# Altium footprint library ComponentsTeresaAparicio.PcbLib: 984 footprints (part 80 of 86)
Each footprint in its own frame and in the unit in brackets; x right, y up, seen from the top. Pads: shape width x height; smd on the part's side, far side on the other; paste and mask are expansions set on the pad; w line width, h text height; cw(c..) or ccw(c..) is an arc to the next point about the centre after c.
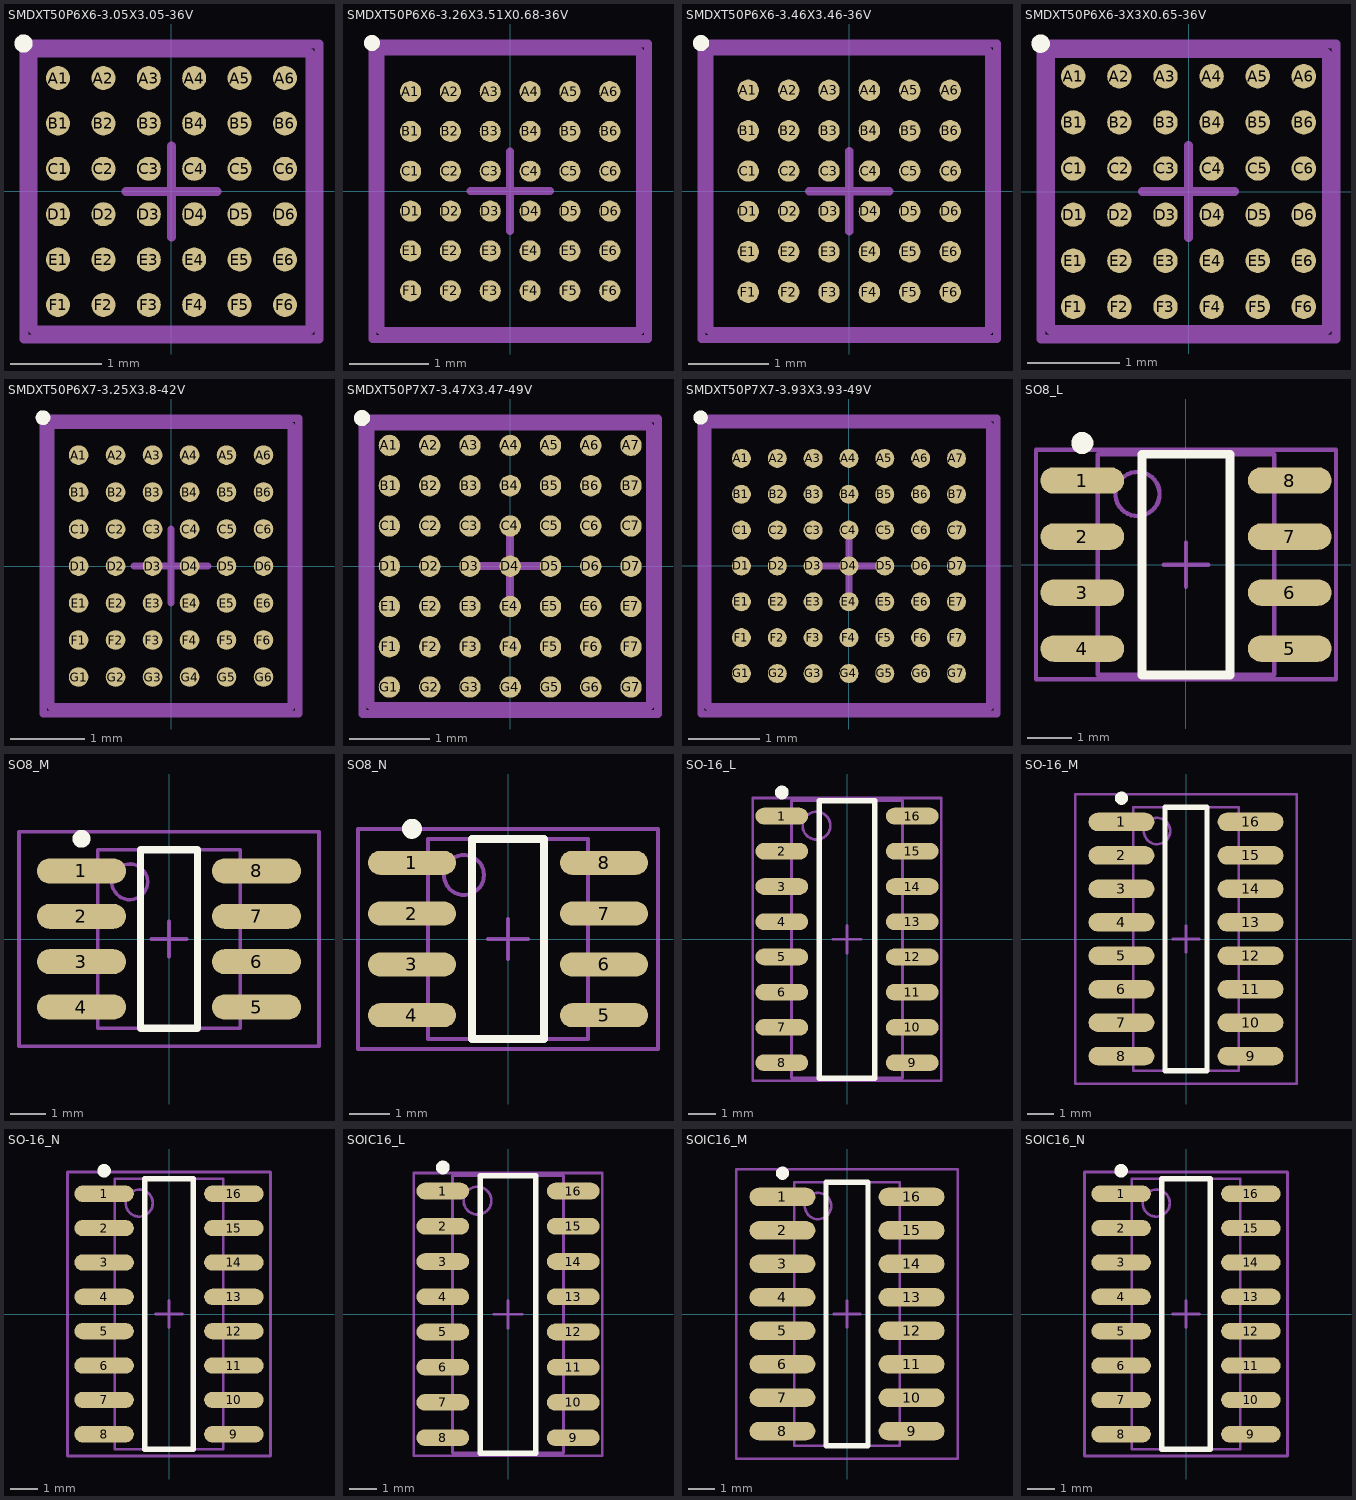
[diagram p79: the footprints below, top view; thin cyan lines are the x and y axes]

## SMDXT50P6X6-3.05X3.05-36V [mm] "Micro SMD, 36-Leads, Body 3.05x3.05mm, Pitch 0.5mm, NSC Recommended"
height 0.73
pads (36):
  round 0.265 smd paste-0.132 mask+0.05: A1(-1.25,1.25) A2(-0.75,1.25) A3(-0.25,1.25) A4(0.25,1.25) A5(0.75,1.25) A6(1.25,1.25) B1(-1.25,0.75) B2(-0.75,0.75) B3(-0.25,0.75) B4(0.25,0.75) B5(0.75,0.75) B6(1.25,0.75) C1(-1.25,0.25) C2(-0.75,0.25) C3(-0.25,0.25) C4(0.25,0.25) C5(0.75,0.25) C6(1.25,0.25) D1(-1.25,-0.25) D2(-0.75,-0.25) D3(-0.25,-0.25) D4(0.25,-0.25) D5(0.75,-0.25) D6(1.25,-0.25) E1(-1.25,-0.75) E2(-0.75,-0.75) E3(-0.25,-0.75) E4(0.25,-0.75) E5(0.75,-0.75) E6(1.25,-0.75) F1(-1.25,-1.25) F2(-0.75,-1.25) F3(-0.25,-1.25) F4(0.25,-1.25) F5(0.75,-1.25) F6(1.25,-1.25)
Top Overlay:
  circle w0.1: c-1.63,1.63 r0.05
Top Paste:
  drawing of 324 lines, arcs and shapes, not listed
Mechanical 13:
  lines w0.1: -1.525,-1.525 1.525,-1.525 1.525,1.525 -1.525,1.525 -1.525,-1.525
Mechanical 15:
  lines w0.1: -0.5,0 0.5,0 ; 0,-0.5 0,0.5 ; -1.625,-1.625 1.625,-1.625 1.625,1.625 -1.625,1.625 -1.625,-1.625
3D body: height 0.73, standoff 0, extent -1.525,-1.525 1.525,1.525

## SMDXT50P6X6-3.26X3.51X0.68-36V [mm] "Micro SMD, 36-Leads, Body 3.51x3.26mm, Pitch 0.5mm, NSC Recommended"
height 0.68
pads (36):
  round 0.265 smd paste-0.132 mask+0.05: A1(-1.25,1.25) A2(-0.75,1.25) A3(-0.25,1.25) A4(0.25,1.25) A5(0.75,1.25) A6(1.25,1.25) B1(-1.25,0.75) B2(-0.75,0.75) B3(-0.25,0.75) B4(0.25,0.75) B5(0.75,0.75) B6(1.25,0.75) C1(-1.25,0.25) C2(-0.75,0.25) C3(-0.25,0.25) C4(0.25,0.25) C5(0.75,0.25) C6(1.25,0.25) D1(-1.25,-0.25) D2(-0.75,-0.25) D3(-0.25,-0.25) D4(0.25,-0.25) D5(0.75,-0.25) D6(1.25,-0.25) E1(-1.25,-0.75) E2(-0.75,-0.75) E3(-0.25,-0.75) E4(0.25,-0.75) E5(0.75,-0.75) E6(1.25,-0.75) F1(-1.25,-1.25) F2(-0.75,-1.25) F3(-0.25,-1.25) F4(0.25,-1.25) F5(0.75,-1.25) F6(1.25,-1.25)
Top Overlay:
  circle w0.1: c-1.735,1.86 r0.05
Top Paste:
  drawing of 324 lines, arcs and shapes, not listed
Mechanical 13:
  lines w0.1: -1.63,-1.755 1.63,-1.755 1.63,1.755 -1.63,1.755 -1.63,-1.755
Mechanical 15:
  lines w0.1: -0.5,0 0.5,0 ; 0,-0.5 0,0.5 ; -1.73,-1.855 1.73,-1.855 1.73,1.855 -1.73,1.855 -1.73,-1.855
3D body: height 0.68, standoff 0, extent -1.63,-1.755 1.63,1.755

## SMDXT50P6X6-3.46X3.46-36V [mm] "Micro SMD, 36-Leads, Body 3.46x3.46mm, Pitch 0.5mm, NSC Recommended"
height 0.68
pads (36):
  round 0.265 smd paste-0.132 mask+0.05: A1(-1.25,1.25) A2(-0.75,1.25) A3(-0.25,1.25) A4(0.25,1.25) A5(0.75,1.25) A6(1.25,1.25) B1(-1.25,0.75) B2(-0.75,0.75) B3(-0.25,0.75) B4(0.25,0.75) B5(0.75,0.75) B6(1.25,0.75) C1(-1.25,0.25) C2(-0.75,0.25) C3(-0.25,0.25) C4(0.25,0.25) C5(0.75,0.25) C6(1.25,0.25) D1(-1.25,-0.25) D2(-0.75,-0.25) D3(-0.25,-0.25) D4(0.25,-0.25) D5(0.75,-0.25) D6(1.25,-0.25) E1(-1.25,-0.75) E2(-0.75,-0.75) E3(-0.25,-0.75) E4(0.25,-0.75) E5(0.75,-0.75) E6(1.25,-0.75) F1(-1.25,-1.25) F2(-0.75,-1.25) F3(-0.25,-1.25) F4(0.25,-1.25) F5(0.75,-1.25) F6(1.25,-1.25)
Top Overlay:
  circle w0.1: c-1.835,1.835 r0.05
Top Paste:
  drawing of 324 lines, arcs and shapes, not listed
Mechanical 13:
  lines w0.1: -1.73,-1.73 1.73,-1.73 1.73,1.73 -1.73,1.73 -1.73,-1.73
Mechanical 15:
  lines w0.1: -0.5,0 0.5,0 ; 0,-0.5 0,0.5 ; -1.83,-1.83 1.83,-1.83 1.83,1.83 -1.83,1.83 -1.83,-1.83
3D body: height 0.68, standoff 0, extent -1.73,-1.73 1.73,1.73

## SMDXT50P6X6-3X3X0.65-36V [mm] "Micro SMD, 36-Leads, Body 3x3mm, Pitch 0.5mm, NSC Recommended"
height 0.73
pads (36):
  round 0.265 smd paste-0.132 mask+0.05: A1(-1.25,1.25) A2(-0.75,1.25) A3(-0.25,1.25) A4(0.25,1.25) A5(0.75,1.25) A6(1.25,1.25) B1(-1.25,0.75) B2(-0.75,0.75) B3(-0.25,0.75) B4(0.25,0.75) B5(0.75,0.75) B6(1.25,0.75) C1(-1.25,0.25) C2(-0.75,0.25) C3(-0.25,0.25) C4(0.25,0.25) C5(0.75,0.25) C6(1.25,0.25) D1(-1.25,-0.25) D2(-0.75,-0.25) D3(-0.25,-0.25) D4(0.25,-0.25) D5(0.75,-0.25) D6(1.25,-0.25) E1(-1.25,-0.75) E2(-0.75,-0.75) E3(-0.25,-0.75) E4(0.25,-0.75) E5(0.75,-0.75) E6(1.25,-0.75) F1(-1.25,-1.25) F2(-0.75,-1.25) F3(-0.25,-1.25) F4(0.25,-1.25) F5(0.75,-1.25) F6(1.25,-1.25)
Top Overlay:
  circle w0.1: c-1.605,1.605 r0.05
Top Paste:
  drawing of 324 lines, arcs and shapes, not listed
Mechanical 13:
  lines w0.1: -1.5,-1.5 -1.5,1.5 1.5,1.5 1.5,-1.5 -1.5,-1.5
Mechanical 15:
  lines w0.1: -0.5,0 0.5,0 ; 0,-0.5 0,0.5 ; -1.6,-1.6 -1.6,1.6 1.6,1.6 1.6,-1.6 -1.6,-1.6
3D body: height 0.73, standoff 0, extent -1.5,-1.5 1.5,1.5

## SMDXT50P6X7-3.25X3.8-42V [mm] "Micro SMD, 42-Leads, Body 3.8x3.25mm, Pitch 0.5mm, NSC Recommended"
height 0.73
pads (42):
  round 0.265 smd paste-0.132 mask+0.05: A1(-1.25,1.5) A2(-0.75,1.5) A3(-0.25,1.5) A4(0.25,1.5) A5(0.75,1.5) A6(1.25,1.5) B1(-1.25,1) B2(-0.75,1) B3(-0.25,1) B4(0.25,1) B5(0.75,1) B6(1.25,1) C1(-1.25,0.5) C2(-0.75,0.5) C3(-0.25,0.5) C4(0.25,0.5) C5(0.75,0.5) C6(1.25,0.5) D1(-1.25,0) D2(-0.75,0) D3(-0.25,0) D4(0.25,0) D5(0.75,0) D6(1.25,0) E1(-1.25,-0.5) E2(-0.75,-0.5) E3(-0.25,-0.5) E4(0.25,-0.5) E5(0.75,-0.5) E6(1.25,-0.5) F1(-1.25,-1) F2(-0.75,-1) F3(-0.25,-1) F4(0.25,-1) F5(0.75,-1) F6(1.25,-1) G1(-1.25,-1.5) G2(-0.75,-1.5) G3(-0.25,-1.5) G4(0.25,-1.5) G5(0.75,-1.5) G6(1.25,-1.5)
Top Overlay:
  circle w0.1: c-1.73,2.005 r0.05
Top Paste:
  drawing of 378 lines, arcs and shapes, not listed
Mechanical 13:
  lines w0.1: -1.625,-1.9 1.625,-1.9 1.625,1.9 -1.625,1.9 -1.625,-1.9
Mechanical 15:
  lines w0.1: -0.5,0 0.5,0 ; 0,-0.5 0,0.5 ; -1.725,-2 1.725,-2 1.725,2 -1.725,2 -1.725,-2
3D body: height 0.73, standoff 0, extent -1.625,-1.9 1.625,1.9

## SMDXT50P7X7-3.47X3.47-49V [mm] "Micro SMD, 49-Leads, Body 3.47x3.47mm, Pitch 0.5mm, NSC Recommended"
height 0.73
pads (49):
  round 0.265 smd paste-0.132 mask+0.05: A1(-1.5,1.5) A2(-1,1.5) A3(-0.5,1.5) A4(0,1.5) A5(0.5,1.5) A6(1,1.5) A7(1.5,1.5) B1(-1.5,1) B2(-1,1) B3(-0.5,1) B4(0,1) B5(0.5,1) B6(1,1) B7(1.5,1) C1(-1.5,0.5) C2(-1,0.5) C3(-0.5,0.5) C4(0,0.5) C5(0.5,0.5) C6(1,0.5) C7(1.5,0.5) D1(-1.5,0) D2(-1,0) D3(-0.5,0) D4(0,0) D5(0.5,0) D6(1,0) D7(1.5,0) E1(-1.5,-0.5) E2(-1,-0.5) E3(-0.5,-0.5) E4(0,-0.5) E5(0.5,-0.5) E6(1,-0.5) E7(1.5,-0.5) F1(-1.5,-1) F2(-1,-1) F3(-0.5,-1) F4(0,-1) F5(0.5,-1) F6(1,-1) F7(1.5,-1) G1(-1.5,-1.5) G2(-1,-1.5) G3(-0.5,-1.5) G4(0,-1.5) G5(0.5,-1.5) G6(1,-1.5) G7(1.5,-1.5)
Top Overlay:
  circle w0.1: c-1.84,1.84 r0.05
Top Paste:
  drawing of 441 lines, arcs and shapes, not listed
Mechanical 13:
  lines w0.1: -1.735,-1.735 -1.735,1.735 1.735,1.735 1.735,-1.735 -1.735,-1.735
Mechanical 15:
  lines w0.1: -0.5,0 0.5,0 ; 0,-0.5 0,0.5 ; -1.835,-1.835 -1.835,1.835 1.835,1.835 1.835,-1.835 -1.835,-1.835
3D body: height 0.73, standoff 0, extent -1.735,-1.735 1.735,1.735

## SMDXT50P7X7-3.93X3.93-49V [mm] "Micro SMD, 49-Leads, Body 3.93x3.93mm, Pitch 0.5mm, NSC Recommended"
height 0.73
pads (49):
  round 0.265 smd paste-0.132 mask+0.05: A1(-1.5,1.5) A2(-1,1.5) A3(-0.5,1.5) A4(0,1.5) A5(0.5,1.5) A6(1,1.5) A7(1.5,1.5) B1(-1.5,1) B2(-1,1) B3(-0.5,1) B4(0,1) B5(0.5,1) B6(1,1) B7(1.5,1) C1(-1.5,0.5) C2(-1,0.5) C3(-0.5,0.5) C4(0,0.5) C5(0.5,0.5) C6(1,0.5) C7(1.5,0.5) D1(-1.5,0) D2(-1,0) D3(-0.5,0) D4(0,0) D5(0.5,0) D6(1,0) D7(1.5,0) E1(-1.5,-0.5) E2(-1,-0.5) E3(-0.5,-0.5) E4(0,-0.5) E5(0.5,-0.5) E6(1,-0.5) E7(1.5,-0.5) F1(-1.5,-1) F2(-1,-1) F3(-0.5,-1) F4(0,-1) F5(0.5,-1) F6(1,-1) F7(1.5,-1) G1(-1.5,-1.5) G2(-1,-1.5) G3(-0.5,-1.5) G4(0,-1.5) G5(0.5,-1.5) G6(1,-1.5) G7(1.5,-1.5)
Top Overlay:
  circle w0.1: c-2.07,2.07 r0.05
Top Paste:
  drawing of 441 lines, arcs and shapes, not listed
Mechanical 13:
  lines w0.1: -1.965,-1.965 1.965,-1.965 1.965,1.965 -1.965,1.965 -1.965,-1.965
Mechanical 15:
  lines w0.1: -0.5,0 0.5,0 ; 0,-0.5 0,0.5 ; -2.065,-2.065 2.065,-2.065 2.065,2.065 -2.065,2.065 -2.065,-2.065
3D body: height 0.73, standoff 0, extent -1.965,-1.965 1.965,1.965

## SO8_L [mm] "SOIC, 8-Leads, Body 4.9x3.9mm, Pitch 1.27mm, IPC High Density"
height 1.75
pads (8):
  oval 1.9x0.6 smd: 1(-2.35,1.905) 2(-2.35,0.635) 3(-2.35,-0.635) 4(-2.35,-1.905) 5(2.35,-1.905) 6(2.35,-0.635) 7(2.35,0.635) 8(2.35,1.905)
Top Overlay:
  circle w0.25: c-2.35,2.755 r0.125
  lines w0.2: -1,-2.5 -1,2.5 1,2.5 1,-2.5 -1,-2.5
Mechanical 13:
  circle w0.1: c-1.1,1.6 r0.5
  lines w0.1: -2,-2.5 -2,2.5 2,2.5 2,-2.5 -2,-2.5
Mechanical 15:
  lines w0.1: -0.5,0 0.5,0 ; 0,-0.5 0,0.5 ; -3.4,-2.6 -3.4,2.6 3.4,2.6 3.4,-2.6 -3.4,-2.6
3D body: height 1.75, standoff 0, extent -2,-2.5 2,2.5

## SO8_M [mm] "SOIC, 8-Leads, Body 4.9x3.9mm, Pitch 1.27mm, IPC Low Density"
height 1.75
pads (8):
  oval 2.5x0.7 smd: 1(-2.45,1.905) 2(-2.45,0.635) 3(-2.45,-0.635) 4(-2.45,-1.905) 5(2.45,-1.905) 6(2.45,-0.635) 7(2.45,0.635) 8(2.45,1.905)
Top Overlay:
  circle w0.25: c-2.45,2.805 r0.125
  lines w0.2: -0.8,-2.5 0.8,-2.5 0.8,2.5 -0.8,2.5 -0.8,-2.5
Mechanical 13:
  circle w0.1: c-1.1,1.6 r0.5
  lines w0.1: -2,-2.5 2,-2.5 2,2.5 -2,2.5 -2,-2.5
Mechanical 15:
  lines w0.1: -0.5,0 0.5,0 ; 0,-0.5 0,0.5 ; -4.2,-3 4.2,-3 4.2,3 -4.2,3 -4.2,-3
3D body: height 1.75, standoff 0, extent -2,-2.5 2,2.5

## SO8_N [mm] "SOIC, 8-Leads, Body 4.9x3.9mm, Pitch 1.27mm, IPC Medium Density"
height 1.75
pads (8):
  oval 2.2x0.6 smd: 1(-2.4,1.905) 2(-2.4,0.635) 3(-2.4,-0.635) 4(-2.4,-1.905) 5(2.4,-1.905) 6(2.4,-0.635) 7(2.4,0.635) 8(2.4,1.905)
Top Overlay:
  circle w0.25: c-2.4,2.755 r0.125
  lines w0.2: -0.9,-2.5 -0.9,2.5 0.9,2.5 0.9,-2.5 -0.9,-2.5
Mechanical 13:
  circle w0.1: c-1.1,1.6 r0.5
  lines w0.1: -2,-2.5 -2,2.5 2,2.5 2,-2.5 -2,-2.5
Mechanical 15:
  lines w0.1: -0.5,0 0.5,0 ; 0,-0.5 0,0.5 ; -3.75,-2.75 -3.75,2.75 3.75,2.75 3.75,-2.75 -3.75,-2.75
3D body: height 1.75, standoff 0, extent -2,-2.5 2,2.5

## SO-16_L [mm] "SOIC, 16-Leads, Body 9.9x3.9mm, Pitch 1.27mm, IPC High Density"
height 1.75
pads (16):
  oval 1.9x0.6 smd: 1(-2.35,4.445) 2(-2.35,3.175) 3(-2.35,1.905) 4(-2.35,0.635) 5(-2.35,-0.635) 6(-2.35,-1.905) 7(-2.35,-3.175) 8(-2.35,-4.445) 9(2.35,-4.445) 10(2.35,-3.175) 11(2.35,-1.905) 12(2.35,-0.635) 13(2.35,0.635) 14(2.35,1.905) 15(2.35,3.175) 16(2.35,4.445)
Top Overlay:
  circle w0.25: c-2.35,5.295 r0.125
  lines w0.2: -1,-5 1,-5 1,5 -1,5 -1,-5
Mechanical 13:
  circle w0.1: c-1.1,4.1 r0.5
  lines w0.1: -2,-5 2,-5 2,5 -2,5 -2,-5
Mechanical 15:
  lines w0.1: -0.5,0 0.5,0 ; 0,-0.5 0,0.5 ; -3.4,-5.1 3.4,-5.1 3.4,5.1 -3.4,5.1 -3.4,-5.1
3D body: height 1.75, standoff 0, extent -2,-5 2,5

## SO-16_M [mm] "SOIC, 16-Leads, Body 9.9x3.9mm, Pitch 1.27mm, IPC Low Density"
height 1.75
pads (16):
  oval 2.5x0.7 smd: 1(-2.45,4.445) 2(-2.45,3.175) 3(-2.45,1.905) 4(-2.45,0.635) 5(-2.45,-0.635) 6(-2.45,-1.905) 7(-2.45,-3.175) 8(-2.45,-4.445) 9(2.45,-4.445) 10(2.45,-3.175) 11(2.45,-1.905) 12(2.45,-0.635) 13(2.45,0.635) 14(2.45,1.905) 15(2.45,3.175) 16(2.45,4.445)
Top Overlay:
  circle w0.25: c-2.45,5.345 r0.125
  lines w0.2: -0.8,-5 -0.8,5 0.8,5 0.8,-5 -0.8,-5
Mechanical 13:
  circle w0.1: c-1.1,4.1 r0.5
  lines w0.1: -2,-5 -2,5 2,5 2,-5 -2,-5
Mechanical 15:
  lines w0.1: -0.5,0 0.5,0 ; 0,-0.5 0,0.5 ; -4.2,-5.5 -4.2,5.5 4.2,5.5 4.2,-5.5 -4.2,-5.5
3D body: height 1.75, standoff 0, extent -2,-5 2,5

## SO-16_N [mm] "SOIC, 16-Leads, Body 9.9x3.9mm, Pitch 1.27mm, IPC Medium Density"
height 1.75
pads (16):
  oval 2.2x0.6 smd: 1(-2.4,4.445) 2(-2.4,3.175) 3(-2.4,1.905) 4(-2.4,0.635) 5(-2.4,-0.635) 6(-2.4,-1.905) 7(-2.4,-3.175) 8(-2.4,-4.445) 9(2.4,-4.445) 10(2.4,-3.175) 11(2.4,-1.905) 12(2.4,-0.635) 13(2.4,0.635) 14(2.4,1.905) 15(2.4,3.175) 16(2.4,4.445)
Top Overlay:
  circle w0.25: c-2.4,5.295 r0.125
  lines w0.2: -0.9,-5 0.9,-5 0.9,5 -0.9,5 -0.9,-5
Mechanical 13:
  circle w0.1: c-1.1,4.1 r0.5
  lines w0.1: -2,-5 2,-5 2,5 -2,5 -2,-5
Mechanical 15:
  lines w0.1: -0.5,0 0.5,0 ; 0,-0.5 0,0.5 ; -3.75,-5.25 3.75,-5.25 3.75,5.25 -3.75,5.25 -3.75,-5.25
3D body: height 1.75, standoff 0, extent -2,-5 2,5

## SOIC16_L [mm] "SOIC, 16-Leads, Body 9.9x3.9mm, Pitch 1.27mm, IPC High Density"
height 1.91
pads (16):
  oval 1.9x0.6 smd: 1(-2.35,4.445) 2(-2.35,3.175) 3(-2.35,1.905) 4(-2.35,0.635) 5(-2.35,-0.635) 6(-2.35,-1.905) 7(-2.35,-3.175) 8(-2.35,-4.445) 9(2.35,-4.445) 10(2.35,-3.175) 11(2.35,-1.905) 12(2.35,-0.635) 13(2.35,0.635) 14(2.35,1.905) 15(2.35,3.175) 16(2.35,4.445)
Top Overlay:
  circle w0.25: c-2.35,5.295 r0.125
  lines w0.2: -1,-5 -1,5 1,5 1,-5 -1,-5
Mechanical 13:
  circle w0.1: c-1.1,4.1 r0.5
  lines w0.1: -2,-5 -2,5 2,5 2,-5 -2,-5
Mechanical 15:
  lines w0.1: -0.5,0 0.5,0 ; 0,-0.5 0,0.5 ; -3.4,-5.1 -3.4,5.1 3.4,5.1 3.4,-5.1 -3.4,-5.1
3D body: height 1.91, standoff 0, extent -2,-5 2,5

## SOIC16_M [mm] "SOIC, 16-Leads, Body 9.9x3.9mm, Pitch 1.27mm, IPC Low Density"
height 1.91
pads (16):
  oval 2.5x0.7 smd: 1(-2.45,4.445) 2(-2.45,3.175) 3(-2.45,1.905) 4(-2.45,0.635) 5(-2.45,-0.635) 6(-2.45,-1.905) 7(-2.45,-3.175) 8(-2.45,-4.445) 9(2.45,-4.445) 10(2.45,-3.175) 11(2.45,-1.905) 12(2.45,-0.635) 13(2.45,0.635) 14(2.45,1.905) 15(2.45,3.175) 16(2.45,4.445)
Top Overlay:
  circle w0.25: c-2.45,5.345 r0.125
  lines w0.2: -0.8,-5 -0.8,5 0.8,5 0.8,-5 -0.8,-5
Mechanical 13:
  circle w0.1: c-1.1,4.1 r0.5
  lines w0.1: -2,-5 -2,5 2,5 2,-5 -2,-5
Mechanical 15:
  lines w0.1: -0.5,0 0.5,0 ; 0,-0.5 0,0.5 ; -4.2,-5.5 -4.2,5.5 4.2,5.5 4.2,-5.5 -4.2,-5.5
3D body: height 1.91, standoff 0, extent -2,-5 2,5

## SOIC16_N [mm] "SOIC, 16-Leads, Body 9.9x3.9mm, Pitch 1.27mm, IPC Medium Density"
height 1.91
pads (16):
  oval 2.2x0.6 smd: 1(-2.4,4.445) 2(-2.4,3.175) 3(-2.4,1.905) 4(-2.4,0.635) 5(-2.4,-0.635) 6(-2.4,-1.905) 7(-2.4,-3.175) 8(-2.4,-4.445) 9(2.4,-4.445) 10(2.4,-3.175) 11(2.4,-1.905) 12(2.4,-0.635) 13(2.4,0.635) 14(2.4,1.905) 15(2.4,3.175) 16(2.4,4.445)
Top Overlay:
  circle w0.25: c-2.4,5.295 r0.125
  lines w0.2: -0.9,-5 -0.9,5 0.9,5 0.9,-5 -0.9,-5
Mechanical 13:
  circle w0.1: c-1.1,4.1 r0.5
  lines w0.1: -2,-5 -2,5 2,5 2,-5 -2,-5
Mechanical 15:
  lines w0.1: -0.5,0 0.5,0 ; 0,-0.5 0,0.5 ; -3.75,-5.25 -3.75,5.25 3.75,5.25 3.75,-5.25 -3.75,-5.25
3D body: height 1.91, standoff 0, extent -2,-5 2,5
